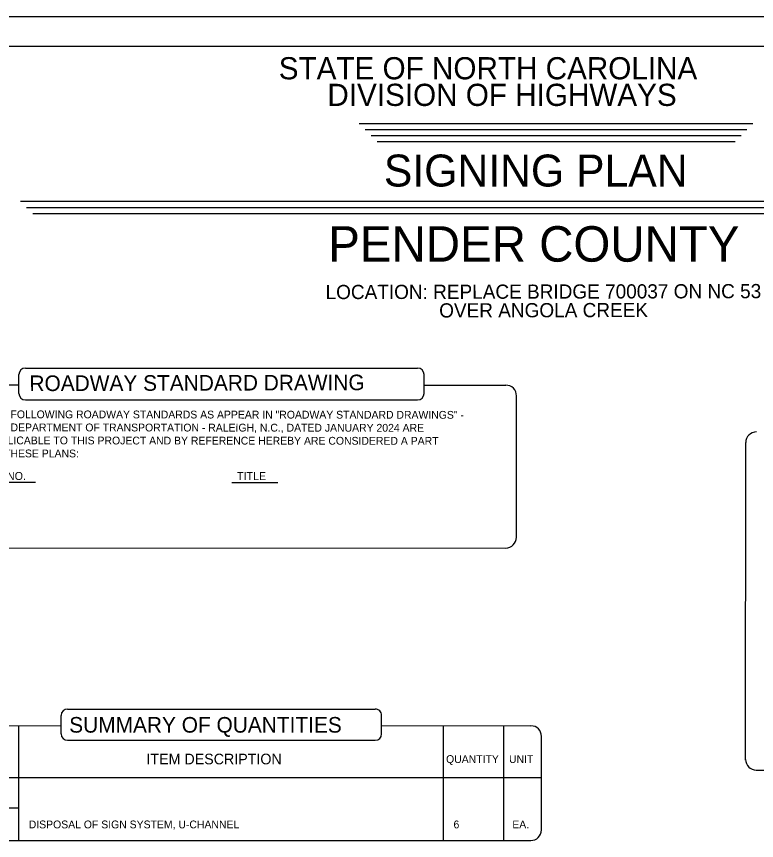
# Model space of a CAD drawing. Extents: x -2362 to 1945, y 0 to 1100.
# Drawn here: x 414 to 1039, y 403 to 1100 of the extents above; entities that cross this region are included whole.
import ezdxf

# ---------------------------------------------------------------- set-up
doc = ezdxf.new("R2010")
doc.units = 0
for name, color, linetype in [('Exist Utilities Telephone Test Hole SUE LOS A CELL', 7, 'Continuous'), ('Sheet Block Title CELL', 7, 'Continuous'), ('Sheet_Plan_CELL', 7, 'Continuous'), ('Sheet_Title_Block_Text', 7, 'Continuous'), ('z - Construction', 7, 'Continuous')]:
    doc.layers.add(name, color=color, linetype=linetype)

msp = doc.modelspace()

# ---------------------------------------------------------------- linework, layer by layer
at = {"layer": 'Exist Utilities Telephone Test Hole SUE LOS A CELL'}
msp.add_line((0, 1100), (1699.98, 1100), dxfattribs=at)
at = {"layer": 'z - Construction'}
for p, q in [((38.08, 1074.94), (1651.98, 1074.94)), ((703.65, 1009.37), (1036.4, 1009.38)), ((708.65, 1004.38), (1031.4, 1004.37)), ((713.65, 999.37), (1026.4, 999.38)), ((718.65, 994.37), (1021.4, 994.38)), ((417.2, 943.68), (1322.86, 943.68)), ((422.34, 938.54), (1317.72, 938.54)), ((427.48, 933.4), (1312.58, 933.4)), ((415.85, 781.19), (415.85, 797.22)), ((758.39, 781.19), (758.39, 797.22)), ((349.05, 788.44), (415.85, 788.41)), ((758.4, 788.25), (827.49, 788.23)), ((836.5, 659.54), (836.57, 779.13)), ((1030.24, 470.99), (1030.36, 739.59)), ((380.72, 706.09), (429.96, 706.07)), ((595.94, 705.99), (634.77, 705.97)), ((348.98, 650.68), (827.41, 650.46)), ((451.56, 493.23), (451.56, 508.94)), ((722.41, 493.23), (722.41, 508.94)), ((297.1, 500.34), (451.56, 500.25)), ((415.72, 403.12), (415.73, 500.27)), ((722.42, 500.28), (848.75, 500.12)), ((774.83, 403.12), (774.85, 500.22)), ((825.78, 403.12), (825.92, 500.15)), ((857.62, 412.12), (857.65, 491.21)), ((1039.29, 462.63), (1513.83, 462.41)), ((288.17, 456.28), (774.84, 456.28)), ((774.84, 456.28), (825.85, 456.28)), ((825.85, 456.28), (857.64, 456.28)), ((288.16, 430.7), (415.72, 430.7)), ((297.05, 403.12), (848.62, 403.12))]:
    msp.add_line(p, q, dxfattribs=at)
for points in [[(421.3, 802.67), (752.94, 802.67)], [(421.3, 775.74), (752.94, 775.74)], [(456.9, 514.28), (717.07, 514.28)], [(456.91, 487.88), (717.07, 487.88)]]:
    msp.add_lwpolyline(points, dxfattribs=at)
for centre, radius, start, end in [((421.3, 797.22), 5.45, 90, 180), ((752.94, 797.22), 5.45, 0, 90), ((827.48, 779.14), 9.09, 359.97341, 89.97341), ((421.3, 781.19), 5.45, 180, 270), ((752.94, 781.19), 5.45, 270, 0), ((1039.45, 739.58), 9.09, 89.97341, 179.97341), ((827.41, 659.55), 9.09, 269.97341, 359.97341), ((456.9, 508.94), 5.35, 90.00664, 180.00664), ((717.07, 508.94), 5.35, 0.00664, 90.00664), ((848.74, 491.21), 8.91, 359.97341, 89.97341), ((456.9, 493.23), 5.35, 180.00664, 270.00664), ((717.07, 493.23), 5.35, 270.00664, 0.00664), ((1039.3, 471.72), 9.09, 179.97341, 269.97341), ((848.62, 412.12), 9, 270, 359.97341)]:
    msp.add_arc(centre, radius, start, end, dxfattribs=at)

# ---------------------------------------------------------------- texts
at = {"layer": 'Sheet Block Title CELL'}
msp.add_text(' PENDER COUNTY', height=30.0001, dxfattribs=at).set_placement((666.2, 892.64))
at = {"layer": 'Sheet_Plan_CELL'}
for s, height, rotation, p in [('THE FOLLOWING ROADWAY STANDARDS AS APPEAR IN "ROADWAY STANDARD DRAWINGS" - ', 6.6, 359.93321, (388.63, 760.27)), ('N.C. DEPARTMENT OF TRANSPORTATION - RALEIGH, N.C., DATED JANUARY 2024 ARE', 6.6, 359.93321, (388.62, 749.24)), ('APPLICABLE TO THIS PROJECT AND BY REFERENCE HEREBY ARE CONSIDERED A PART', 6.6, 359.93321, (388.61, 738.22)), ('OF THESE PLANS:', 6.6, 359.93321, (388.59, 727.2)), ('STD. NO.', 6.771, 359.97341, (382.56, 708.05)), ('TITLE', 6.771, 359.97341, (600.21, 707.95))]:
    msp.add_text(s, height=height, rotation=rotation, dxfattribs=at).set_placement(p)
for s, height, p in [('ITEM DESCRIPTION', 9, (523.7, 467.55)), ('QUANTITY', 6.6, (776.98, 468.68)), ('UNIT', 6.6, (830.23, 468.68)), ('DISPOSAL OF SIGN SYSTEM, U-CHANNEL', 6.6, (424.14, 413.42)), ('6', 6.6, (783.28, 413.42)), ('EA.', 6.6, (832.99, 413.42))]:
    msp.add_text(s, height=height, dxfattribs=at).set_placement(p)
at = {"layer": 'Sheet_Title_Block_Text'}
for s, height, rotation, p in [('SIGNING PLAN', 26.9979, 0.00003, (724.38, 956.21)), ('LOCATION: REPLACE BRIDGE 700037 ON NC 53', 12, 0.12484, (675.13, 860.96)), ('OVER ANGOLA CREEK', 12, 0.12484, (771.17, 845.42)), ('ROADWAY STANDARD DRAWING', 13.2, 0.15565, (424.76, 783.18)), ('SUMMARY OF QUANTITIES', 13.2, 360, (458.36, 494.36))]:
    msp.add_text(s, height=height, rotation=rotation, dxfattribs=at).set_placement(p)
at = {"layer": 'z - Construction'}
for s, p in [('STATE OF NORTH CAROLINA', (635.52, 1046.85)), ('DIVISION OF HIGHWAYS', (676.63, 1024.35))]:
    msp.add_text(s, height=18.7499, dxfattribs=at).set_placement(p)

doc.saveas('drawing.dxf')
